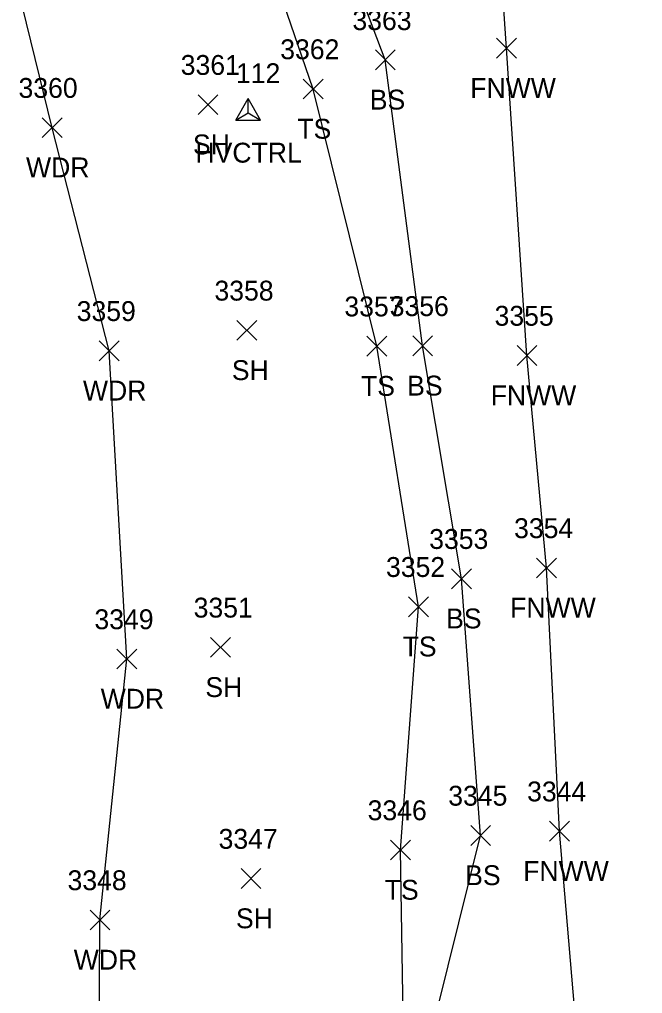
# Model space of a CAD drawing. Extents: x 1650221 to 1650634, y 244606 to 249996.
# Drawn here: x 1650440.4 to 1650503.1, y 246327.1 to 246425.2 of the extents above; entities that cross this region are included whole.
import ezdxf

# ---------------------------------------------------------------- set-up
doc = ezdxf.new("R2010")
doc.units = 0
for name, color, linetype in [('C_A', 7, 'Continuous'), ('C_I', 7, 'Continuous'), ('CPSM', 7, 'Continuous'), ('L_A', 7, 'Continuous'), ('L_I', 7, 'Continuous'), ('L_TIC', 7, 'Continuous'), ('LAWA', 7, 'Continuous'), ('LELB', 7, 'Continuous'), ('LFNC', 7, 'Continuous'), ('LSOGP', 7, 'Continuous')]:
    doc.layers.add(name, color=color, linetype=linetype)

msp = doc.modelspace()

# ---------------------------------------------------------------- linework, layer by layer
at = {"layer": 'CPSM'}
for p, q in [((1650462.134, 246415.049), (1650463.384, 246417.214)), ((1650464.634, 246415.049), (1650463.384, 246417.214)), ((1650463.385, 246415.771), (1650463.384, 246417.214)), ((1650462.134, 246415.049), (1650463.385, 246415.771)), ((1650463.385, 246415.771), (1650463.385, 246415.771)), ((1650463.385, 246415.771), (1650464.634, 246415.049)), ((1650462.134, 246415.049), (1650464.634, 246415.049))]:
    msp.add_line(p, q, dxfattribs=at)
at = {"layer": 'L_TIC'}
for points in [[(1650488.384, 246421.281), (1650490.384, 246423.281)], [(1650490.384, 246421.281), (1650488.384, 246423.281)], [(1650476.18, 246420.111), (1650478.18, 246422.111)], [(1650478.18, 246420.111), (1650476.18, 246422.111)], [(1650468.918, 246417.179), (1650470.918, 246419.179)], [(1650470.918, 246417.179), (1650468.918, 246419.179)], [(1650458.339, 246415.601), (1650460.339, 246417.601)], [(1650460.339, 246415.601), (1650458.339, 246417.601)], [(1650442.671, 246413.288), (1650444.671, 246415.288)], [(1650444.671, 246413.288), (1650442.671, 246415.288)], [(1650462.251, 246392.883), (1650464.251, 246394.883)], [(1650464.251, 246392.883), (1650462.251, 246394.883)], [(1650475.324, 246391.292), (1650477.324, 246393.292)], [(1650477.324, 246391.292), (1650475.324, 246393.292)], [(1650479.94, 246391.324), (1650481.94, 246393.324)], [(1650481.94, 246391.324), (1650479.94, 246393.324)], [(1650448.397, 246390.825), (1650450.397, 246392.825)], [(1650450.397, 246390.825), (1650448.397, 246392.825)], [(1650490.436, 246390.352), (1650492.436, 246392.352)], [(1650492.436, 246390.352), (1650490.436, 246392.352)], [(1650492.398, 246368.972), (1650494.398, 246370.972)], [(1650494.398, 246368.972), (1650492.398, 246370.972)], [(1650483.859, 246367.885), (1650485.859, 246369.885)], [(1650485.859, 246367.885), (1650483.859, 246369.885)], [(1650479.513, 246365.065), (1650481.513, 246367.065)], [(1650481.513, 246365.065), (1650479.513, 246367.065)], [(1650459.591, 246360.976), (1650461.591, 246362.976)], [(1650461.591, 246360.976), (1650459.591, 246362.976)], [(1650450.184, 246359.806), (1650452.184, 246361.806)], [(1650452.184, 246359.806), (1650450.184, 246361.806)], [(1650493.71, 246342.473), (1650495.71, 246344.473)], [(1650495.71, 246342.473), (1650493.71, 246344.473)], [(1650485.776, 246342.044), (1650487.776, 246344.044)], [(1650487.776, 246342.044), (1650485.776, 246344.044)], [(1650477.718, 246340.576), (1650479.718, 246342.576)], [(1650479.718, 246340.576), (1650477.718, 246342.576)], [(1650462.666, 246337.702), (1650464.666, 246339.702)], [(1650464.666, 246337.702), (1650462.666, 246339.702)], [(1650447.47, 246333.537), (1650449.47, 246335.537)], [(1650449.47, 246333.537), (1650447.47, 246335.537)]]:
    msp.add_lwpolyline(points, dxfattribs=at)
at = {"layer": 'LAWA'}
msp.add_lwpolyline([(1650467.45, 246241.248), (1650457.439, 246253.738), (1650465.182, 246273.586), (1650462.121, 246310.217), (1650448.311, 246306.896), (1650448.47, 246334.537), (1650451.184, 246360.806), (1650449.397, 246391.825), (1650443.671, 246414.288), (1650436.755, 246442.34), (1650433.959, 246470.022), (1650430.335, 246504.777), (1650427.125, 246530.837), (1650425.665, 246560.118), (1650421.393, 246581.34), (1650411.429, 246590.247), (1650407.773, 246596.466), (1650408.993, 246611.27), (1650406.472, 246635.271)], dxfattribs=at)
at = {"layer": 'LELB'}
for points in [[(1650479.188, 246312.479), (1650486.776, 246343.044), (1650484.859, 246368.885), (1650480.94, 246392.324), (1650477.18, 246421.111), (1650468.88, 246443.019), (1650461.433, 246474.295), (1650459.987, 246504.257), (1650455.481, 246533.7), (1650468.385, 246557.946), (1650462.638, 246596.825), (1650458.651, 246616.056), (1650445.954, 246610.519), (1650432.734, 246599.274), (1650420.879, 246596.785), (1650423.867, 246613.471), (1650428.269, 246642.152), (1650440.667, 246654.815), (1650470.876, 246672.082), (1650450.604, 246689.528), (1650437.538, 246708.061), (1650451.689, 246713.269), (1650467.717, 246712.4)], [(1650479.188, 246312.479), (1650478.718, 246341.576), (1650480.513, 246366.065), (1650476.324, 246392.292), (1650469.918, 246418.179), (1650461.39, 246442.984), (1650452.285, 246471.601), (1650451.912, 246505.834), (1650450.213, 246533.171), (1650459.886, 246559.372), (1650456.989, 246596.575), (1650458.651, 246616.056)]]:
    msp.add_lwpolyline(points, dxfattribs=at)
at = {"layer": 'LFNC'}
msp.add_lwpolyline([(1650503.061, 246228.044), (1650500.954, 246260.243), (1650499.519, 246280.975), (1650496.753, 246319.425), (1650494.71, 246343.473), (1650493.398, 246369.972), (1650491.436, 246391.352), (1650489.384, 246422.281), (1650487.801, 246445.43), (1650485.635, 246474.807), (1650483.603, 246501.147), (1650481.033, 246533.542), (1650479.368, 246558.298), (1650476.368, 246602.099), (1650473.826, 246635.822)], dxfattribs=at)
at = {"layer": 'LSOGP'}
msp.add_lwpolyline([(1650503.061, 246228.044), (1650500.954, 246260.243), (1650499.519, 246280.975), (1650496.753, 246319.425), (1650494.71, 246343.473), (1650493.398, 246369.972), (1650491.436, 246391.352), (1650489.384, 246422.281), (1650487.801, 246445.43), (1650485.635, 246474.807), (1650483.603, 246501.147), (1650481.033, 246533.542), (1650479.368, 246558.298), (1650476.368, 246602.099), (1650473.826, 246635.822)], dxfattribs=at)

# ---------------------------------------------------------------- texts
at = {"layer": 'C_A'}
msp.add_text('HVCTRL', height=2, dxfattribs=at).set_placement((1650458.078, 246410.771))
at = {"layer": 'C_I'}
msp.add_text('112', height=2, dxfattribs=at).set_placement((1650462.156, 246418.771))
at = {"layer": 'L_A'}
for s, p in [('FNWW', (1650485.731, 246417.281)), ('BS', (1650475.621, 246416.111)), ('TS', (1650468.327, 246413.179)), ('SH', (1650457.827, 246411.601)), ('WDR', (1650441.033, 246409.288)), ('SH', (1650461.739, 246388.883)), ('TS', (1650474.734, 246387.292)), ('BS', (1650479.381, 246387.324)), ('WDR', (1650446.76, 246386.825)), ('FNWW', (1650487.783, 246386.352)), ('FNWW', (1650489.745, 246364.972)), ('BS', (1650483.299, 246363.885)), ('TS', (1650478.922, 246361.065)), ('SH', (1650459.079, 246356.976)), ('WDR', (1650448.546, 246355.806)), ('FNWW', (1650491.057, 246338.473)), ('BS', (1650485.217, 246338.044)), ('TS', (1650477.127, 246336.576)), ('SH', (1650462.155, 246333.702)), ('WDR', (1650445.832, 246329.537))]:
    msp.add_text(s, height=2, dxfattribs=at).set_placement(p)
at = {"layer": 'L_I'}
for s, p in [('3363', (1650473.873, 246424.111)), ('3362', (1650466.611, 246421.179)), ('3361', (1650456.599, 246419.601)), ('3360', (1650440.277, 246417.288)), ('3358', (1650459.991, 246396.883)), ('3357', (1650473.064, 246395.292)), ('3356', (1650477.625, 246395.324)), ('3359', (1650446.13, 246394.825)), ('3355', (1650488.176, 246394.352)), ('3354', (1650490.138, 246372.972)), ('3353', (1650481.599, 246371.885)), ('3352', (1650477.253, 246369.065)), ('3351', (1650457.898, 246364.976)), ('3349', (1650447.916, 246363.806)), ('3345', (1650483.516, 246346.044)), ('3344', (1650491.45, 246346.473)), ('3346', (1650475.403, 246344.576)), ('3347', (1650460.407, 246341.702)), ('3348', (1650445.21, 246337.537))]:
    msp.add_text(s, height=2, dxfattribs=at).set_placement(p)

doc.saveas('drawing.dxf')
